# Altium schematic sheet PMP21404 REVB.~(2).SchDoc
size 431 x 279 mm; Date: Not shown in title block; ApprovedBy: Not shown in title block; CheckedBy: Not shown in title block; Author: Not shown in title block; CompanyName: Not shown in title block; Engineer: Not shown in title block; Organization: Not shown in title block; Address1: Not shown in title block; Address2: Not shown in title block; Address3: Not shown in title block; Address4: Not shown in title block; DocumentNumber: 1; Revision: Use project parameter SCH_Rev; SheetNumber: 1; SheetTotal: 1; PageSetup: Record=PageOptions¦CenterHorizontal=True¦CenterVertical=True¦PrintScale=1.00¦XCorrection=1.00¦YCorrection=1.00¦PrintKind=0¦BorderSize=5000000¦LeftOffset=0¦BottomOffset=0¦Orientation=2¦PaperLength=1000¦PaperWidth=1000¦Scale=100¦PaperSource=15¦PrintQuality=600¦MediaType=1¦DitherType=10¦PaperKind=Letter¦PrintScaleMode=1
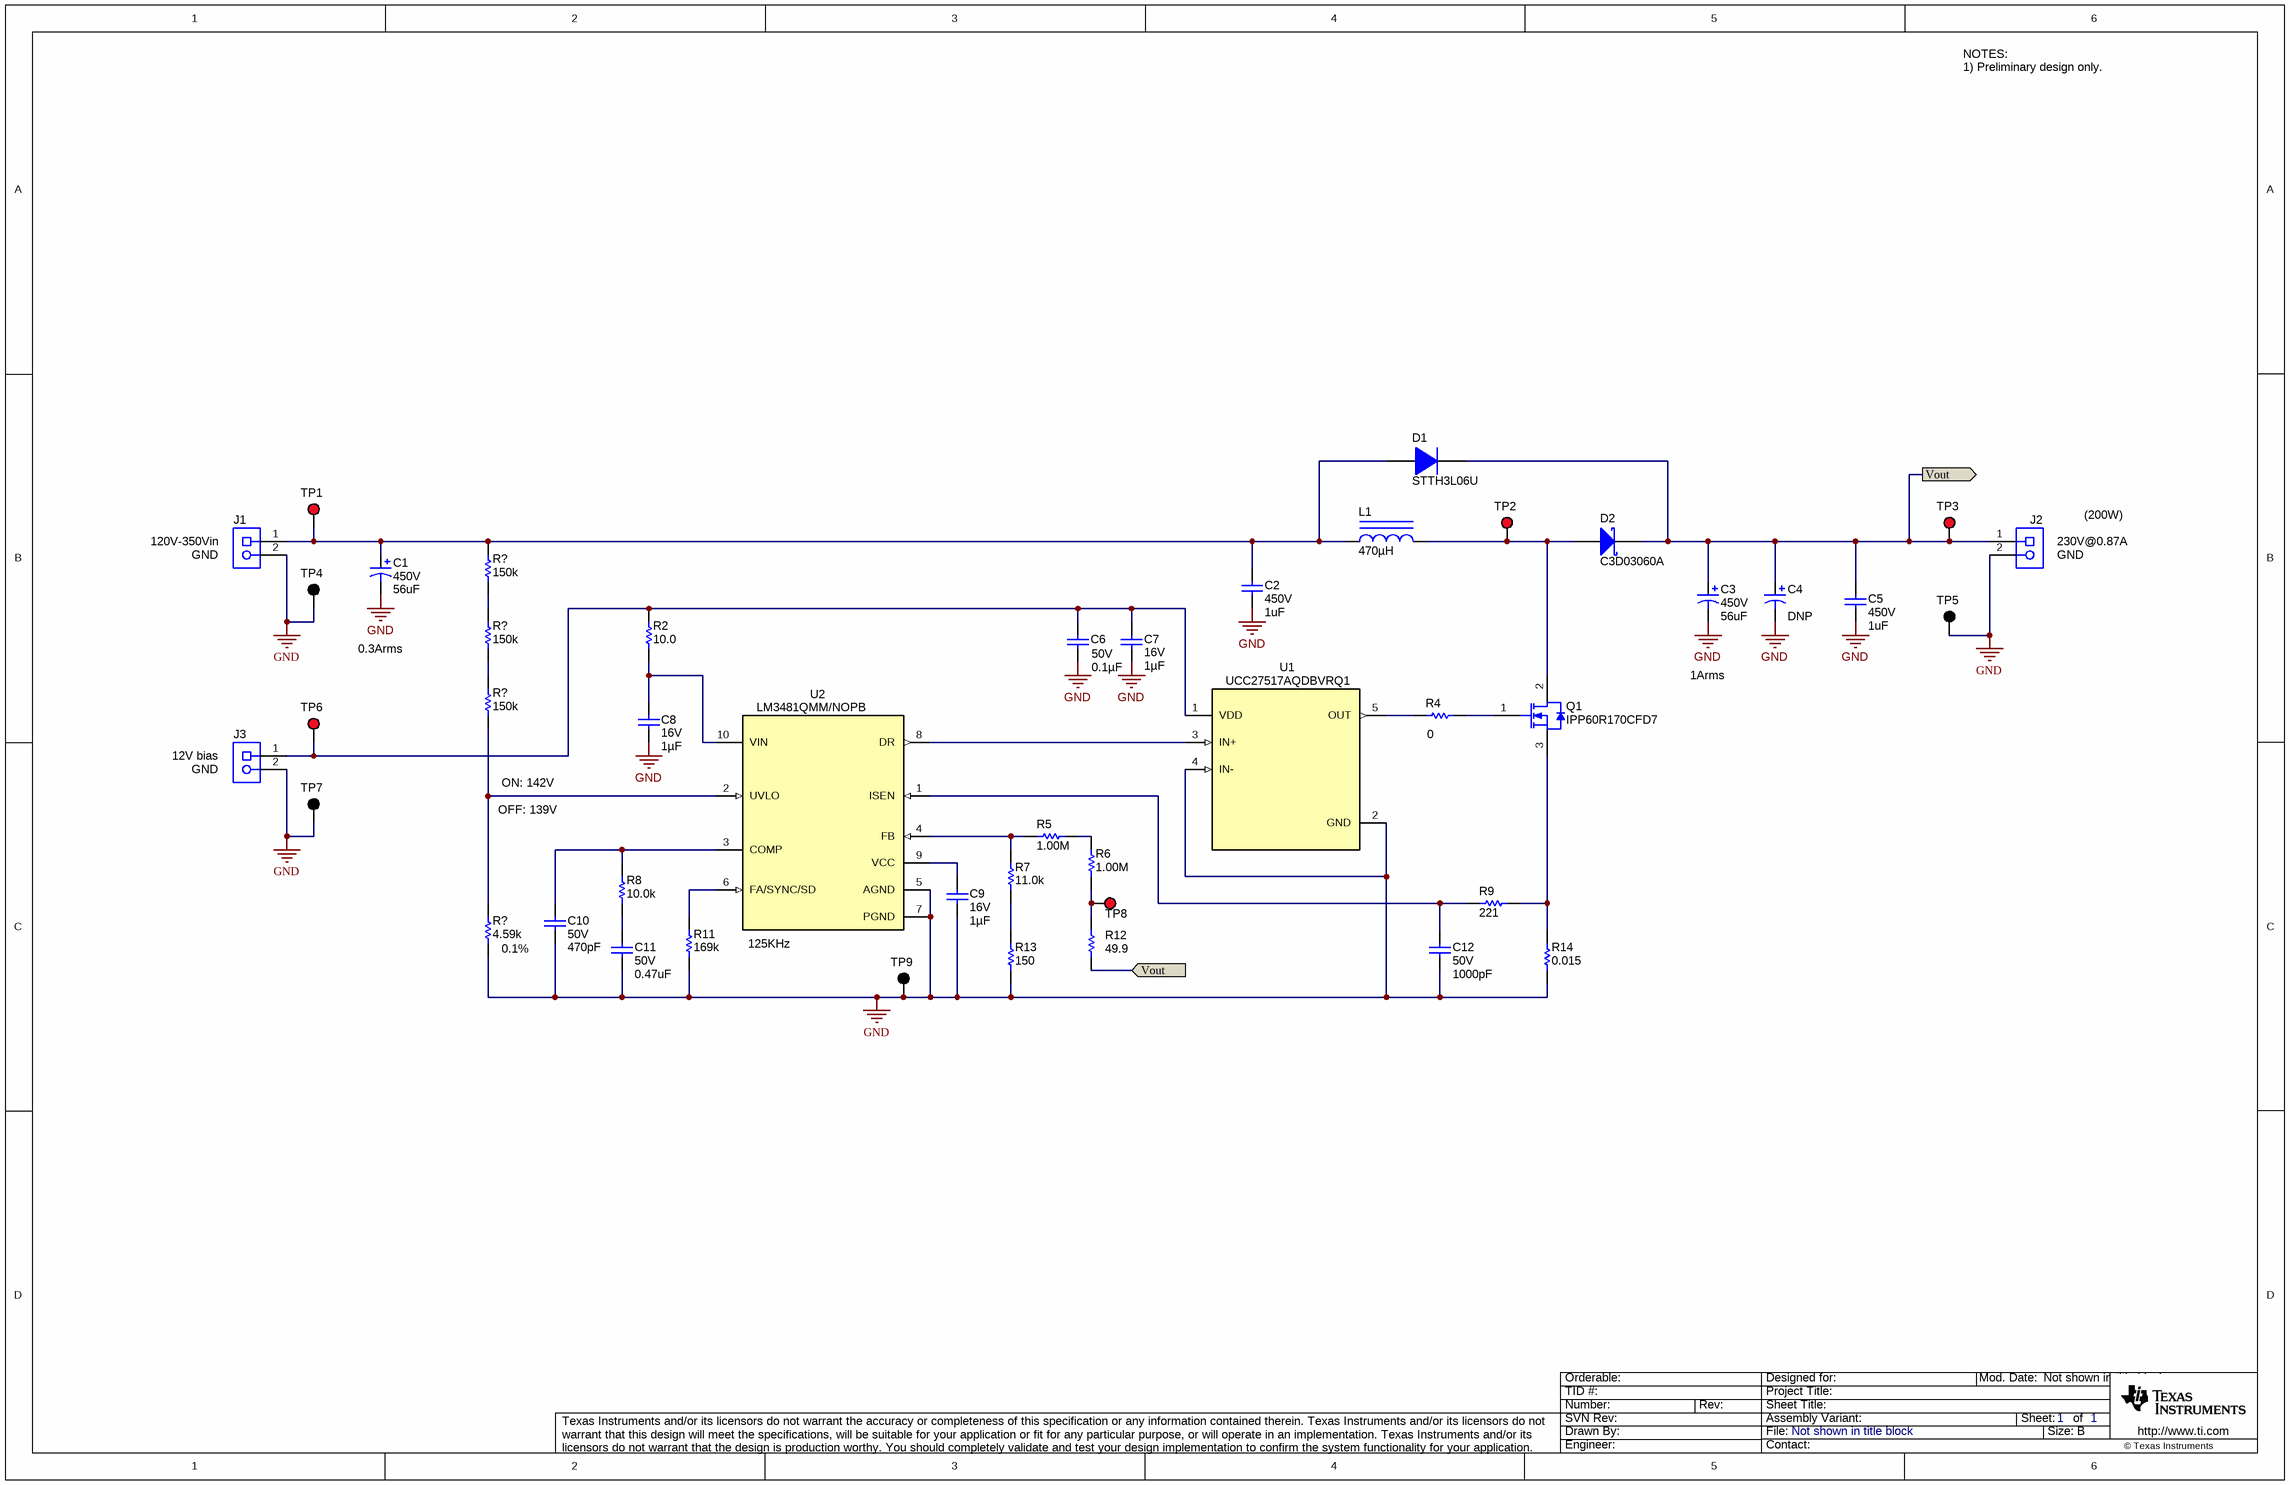
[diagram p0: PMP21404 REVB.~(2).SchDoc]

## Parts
(Parts that share a designator on the sheet are numbered #1, #2 ... from top to bottom, then left to right.)
C1  VDC_V: 450V  ValueDisplayed: 56uF  [Nichicon_2000x2500_Snap]  (hidden comment: LLS2W560MELY)
C2  VDC_V: 450V  ValueDisplayed: 1uF  [MPK_1800x950]  (hidden comment: 450MPK105J)
C3  VDC_V: 450V  ValueDisplayed: 56uF  [Nichicon_2000x2500_Snap]  (hidden comment: LLS2W560MELY)
C4  ValueDisplayed: DNP  [Nichicon_2000x2500_Snap]
C5  VDC_V: 450V  ValueDisplayed: 1uF  [MPK_1800x950]  (hidden comment: 450MPK105J)
C6  VDC_V: 50V  ValueDisplayed: 0.1µF  [0603]  (hidden comment: C0603C104K5RACAUTO)
C7  VDC_V: 16V  ValueDisplayed: 1µF  [0603]  (hidden comment: CGA3E1X7R1C105K080AC)
C8  VDC_V: 16V  ValueDisplayed: 1µF  [0603]  (hidden comment: CGA3E1X7R1C105K080AC)
C9  VDC_V: 16V  ValueDisplayed: 1µF  [0603]  (hidden comment: CGA3E1X7R1C105K080AC)
C10  VDC_V: 50V  ValueDisplayed: 470pF  [0603]  (hidden comment: GRM188R71H471KA01D)
C11  VDC_V: 50V  ValueDisplayed: 0.47uF  [0603]  (hidden comment: CGA3E3X7R1H474K080AB)
C12  VDC_V: 50V  ValueDisplayed: 1000pF  [0603]  (hidden comment: GRM188R71H102JA01D)
D1  STTH3L06U  [SMB]
D2  C3D03060A  [TO-220-2]
J1  Receptacle_2x1  [TERM_BLK_ED555-2DS]  (value not drawn)
J2  Receptacle_2x1  [TERM_BLK_ED555-2DS]  (value not drawn)
J3  Receptacle_2x1  [TERM_BLK_ED555-2DS]  (value not drawn)
L1  ValueDisplayed: 470µH  [Renco_RL1256-3_Pitch_750]  (hidden comment: RL-1256-3-470)
Q1  IPP60R170CFD7  [TO-220AB]
R2  ValueDisplayed: 10.0  [0603]  (hidden comment: CRCW060310R0FKEA)
R4  ValueDisplayed: 0  [0603]  (hidden comment: CRCW06030000Z0EA)
R5  ValueDisplayed: 1.00M  [1206]  (hidden comment: CRCW12061M00FKEA)
R6  ValueDisplayed: 1.00M  [1206]  (hidden comment: CRCW12061M00FKEA)
R7  ValueDisplayed: 11.0k  [0603]  (hidden comment: CRCW060311K0FKEA)
R8  ValueDisplayed: 10.0k  [0603]  (hidden comment: CRCW060310K0FKEA)
R9  value 221  [0603L]  (hidden comment: Resistor)
R11  ValueDisplayed: 169k  [0603]  (hidden comment: CRCW0603169KFKEA)
R12  value 49.9  [0603L]  (hidden comment: Resistor)
R13  ValueDisplayed: 150  [0603]  (hidden comment: CRCW0603150RFKEA)
R14  ValueDisplayed: 0.015  [1206]  (hidden comment: WSLP1206R0150FEA)
R?#1  ValueDisplayed: 150k  [1206]  (hidden comment: CRCW1206150KFKEA)
R?#2  ValueDisplayed: 150k  [1206]  (hidden comment: CRCW1206150KFKEA)
R?#3  ValueDisplayed: 150k  [1206]  (hidden comment: CRCW1206150KFKEA)
R?#4  Tolerance_%: 0.1%  ValueDisplayed: 4.59k  [0603]  (hidden comment: RT0603BRD074K59L)
TP1  5000  [Keystone5000]  (value not drawn)
TP2  5000  [Keystone5000]  (value not drawn)
TP3  5000  [Keystone5000]  (value not drawn)
TP4  5001  [Keystone5001]  (value not drawn)
TP5  5001  [Keystone5001]  (value not drawn)
TP6  5000  [Keystone5000]  (value not drawn)
TP7  5001  [Keystone5001]  (value not drawn)
TP8  5000  [Keystone5000]  (value not drawn)
TP9  5001  [Keystone5001]  (value not drawn)
U1  UCC27517AQDBVRQ1  [DBV0005A_N]
U2  LM3481QMM/NOPB  [DGS0010A_N]

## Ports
Vout

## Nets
GND: C1.2(-) C2.2 C3.2(-) C4.2(-) C5.2 C6.2 C7.2 C8.2 C9.2 C10.2 C11.2 C12.2 J1.2 J2.2 J3.2 R11.1 R13.1 R14.1 R?#4.1 TP4.1 TP5.1 TP7.1 TP9.1 U1.2(GND) U1.4(IN-) U2.5(AGND) U2.7(PGND)
Vout: C3.1(+) C4.1(+) C5.1 D1.1(K) D2.1(K) J2.1 R12.1 TP3.1 ; port Vout
NetC1_1: C1.1(+) C2.1 D1.2(A) J1.1 L1.1 R?#1.2 TP1.1
NetC6_1: C6.1 C7.1 J3.1 R2.1 TP6.1 U1.1(VDD)
NetC8_1: C8.1 R2.2 U2.10(VIN)
NetC9_1: C9.1 U2.9(VCC)
NetC10_1: C10.1 R8.2 U2.3(COMP)
NetC11_1: C11.1 R8.1
NetC12_1: C12.1 R9.2 U2.1(ISEN)
NetD2_2: D2.2(A) L1.2 Q1.2(D) TP2.1
NetQ1_1: Q1.1(G) R4.2
NetQ1_3: Q1.3(S) R9.1 R14.2
NetR4_1: R4.1 U1.5(OUT)
NetR5_1: R5.1 R7.2 U2.4(FB)
NetR5_2: R5.2 R6.2
NetR6_1: R6.1 R12.2 TP8.1
NetR7_1: R7.1 R13.2
NetR11_2: R11.2 U2.6(FA/SYNC/SD)
NetR?#1_1: R?#1.1 R?#2.2
NetR?#2_1: R?#2.1 R?#3.2
NetR?#3_1: R?#3.1 R?#4.2 U2.2(UVLO)
NetU1_3: U1.3(IN+) U2.8(DR)

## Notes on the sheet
- NOTES:
  1) Preliminary design only.
- (near J1) 120V-350Vin
- (near J1) GND
- (near J2) 230V@0.87A
- (near J2) GND
- (200W)
- 0.3Arms
- 1Arms
- (near J3) 12V bias
- (near J3) GND
- ON: 142V
- OFF: 139V
- (near U2) 125KHz

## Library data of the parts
C1 C3 = CMP-0010119-2: CAP, AL, 56 uF, 450 V, +/- 20%, TH; Manufacturer: Nichicon; TaMin_C: -25°C; Polarized: Y; SizeAreaWB_mm2: 484; Value1: Unknown; U/M: EA; Value: 56uF; TaMax_C: 85°C; SizeZ_mm: 27; SizeX_mm: 20; Cap_Case: 20x25mm; SizeArea_mm2: 400; CompType: Capacitor; AEC Qualified: N; Cap_F: 56µF; IRMS_A: 6.1dA; AEC Category: Q200
C2 C5 = CMP-0012307-3: CAP, Film, 1 uF, 450 V, +/- 5%, TH; Manufacturer: Rubycon; TaMin_C: -40°C; Polarized: N; Value1: Unknown; Value: 1uF; TaMax_C: 105°C; Cap_Case: 18x9.5mm; Cap_F: 1µF; AEC Category: Q200
C4 = CMP-0010119-2: CAP, AL, DNP; TaMin_C: -25°C; Polarized: Y; SizeAreaWB_mm2: 484; Value1: Unknown; U/M: EA; TaMax_C: 85°C; Tolerance_%: 20%; SizeZ_mm: 27; SizeX_mm: 20; Cap_Case: 20x25mm; SizeArea_mm2: 400; CompType: Capacitor; AEC Qualified: N; AEC Category: Q200
C6 = CMP-0079602-1: CAP, CERM, 0.1 µF, 50 V,+/- 10%, X7R, AEC-Q200 Grade 1, 0603; Manufacturer: Kemet; TaMin_C: -55°C; Polarized: N; SizeAreaWB_mm2: 4.68; U/M: EA; Value: 0.1uF; TaMax_C: 125°C; SizeZ_mm: 1; SizeX_mm: 1.6; SizeY_mm: 0.8; SizeArea_mm2: 1.28; CompType: Capacitor; AEC Qualified: Y; Cap_F: 100nF; AEC Category: Q200
C7-C9 = CMP-0079607-1: CAP, CERM, 1 µF, 16 V,+/- 10%, X7R, AEC-Q200 Grade 1, 0603; Manufacturer: TDK; TaMin_C: -55°C; Polarized: N; SizeAreaWB_mm2: 4.68; U/M: EA; Value: 1uF; TaMax_C: 125°C; SizeZ_mm: 1; SizeX_mm: 1.6; SizeY_mm: 0.8; SizeArea_mm2: 1.28; AEC Qualified: Y; AEC Category: Q200
C10 = CMP-0007455-4: CAP, CERM, 470 pF, 50 V, +/- 10%, X7R, 0603; Manufacturer: MuRata; TaMin_C: -55°C; Polarized: N; SizeAreaWB_mm2: 4.68; Value1: Unknown; U/M: EA; Value: 470pF; TaMax_C: 125°C; SizeZ_mm: 1; SizeX_mm: 1.6; SizeY_mm: 0.8; SizeArea_mm2: 1.28; AEC Category: Q200
C11 = CMP-0007096-4: CAP, CERM, 0.47 uF, 50 V, +/- 10%, X7R, AEC-Q200 Grade 1, 0603; Manufacturer: TDK; TaMin_C: -55°C; ESR_ohm: 0.01064; Polarized: N; SizeAreaWB_mm2: 4.68; Value1: 0.01064 ohm; U/M: EA; Value: 0.47uF; TaMax_C: 125°C; SizeZ_mm: 1; SizeX_mm: 1.6; SizeY_mm: 0.8; SizeArea_mm2: 1.28; AEC Qualified: Y; Cap_F: 470nF; IRMS_A: 1.59966A; AEC Category: Q200
C12 = CMP-0007431-4: CAP, CERM, 1000 pF, 50 V, +/- 5%, X7R, 0603; Manufacturer: MuRata; TaMin_C: -55°C; Polarized: N; SizeAreaWB_mm2: 4.68; Value1: Unknown; U/M: EA; Value: 1000pF; TaMax_C: 125°C; SizeZ_mm: 1; SizeX_mm: 1.6; SizeY_mm: 0.8; SizeArea_mm2: 1.28; Cap_F: 1nF; AEC Category: Q200
D1 = CMP-0077014-1: Diode, Ultrafast, 600 V, 3 A, SMB; Manufacturer: STMicroelectronics; SizeAreaWB_mm2: 44.156; Vr_V: 600V; SizeArea_mm2: 21.336; TJmax_C: 175°C; AEC Category: Q101; Value: 600V; SizeZ_mm: 2.6; Green_REACh: Incomplete; Io_A: 3A; Vf_V: 1.3V; SizeY_mm: 3.81; Green_Lifecycle: Not Set; U/M: EA; SizeX_mm: 5.6
D2 = CMP-0079543-1: Diode, Schottky, 600 V, 11 A, AEC-Q101, TH; Manufacturer: Cree; SizeAreaWB_mm2: 77.630025; Vr_V: 600V; SizeArea_mm2: 44.650025; AEC Qualified: Y; TJmax_C: 175°C; AEC Category: Q101; Value: 600V; SizeZ_mm: 20; Green_REACh: Incomplete; Io_A: 11A; SizeY_mm: 4.445; Green_Lifecycle: Active; SizeX_mm: 10.045; RJC_CperW: 3.2
J1-J3 = CMP-0074913-1: Terminal Block, 3.5mm Pitch, 2x1, TH; PartNumber: ED555/2DS; Manufacturer: On-Shore Technology; Cert_CULUS: Y; CNHeader: False; ContactFinish: Brass; CT: True; Current_A: 6A; Gender: Female; Green_Lifecycle: Active; Green_REACh: Passed; Pitch_mm: 3.5; Row_Count: 1; Shrouded: N; Voltage_V: 150V
L1 = CMP-0077831-1: Inductor, 470 µH, 4 A, 0.187 ohm, TH; Manufacturer: Renco Electronics; SizeAreaWB_mm2: 896.4036; Irms: 4A @ 40C rise; SizeArea_mm2: 780.6436; AEC Qualified: N; AEC Category: Q200; Value: 470uH; SizeZ_mm: 21.59; Imax_A: 4A; SizeY_mm: 27.94; Isat: 6A @ 5% inductance drop; DCR_ohm: 1.87d
Q1 = CMP-0001174-3: MOSFET, N-CH, 600 V, 51 A, TO-220AB; Alternate Manufacturer: None; Manufacturer: Infineon Technologies; SizeZ_mm: 19.4; ChType: N; Value2: 28 nC; VdsMax_V: 600V; SizeX_mm: 10.2; SizeY_mm: 4.5; Vgs_V: 20V; Value: 600V; SizeArea_mm2: 45.9; AEC Category: Q101; IdsMax_A: 51A; SizeAreaWB_mm2: 79.3; U/M: EA; QgTyp_nC: 28
R2 = CMP-0022003-4: RES, 10.0, 1%, 0.1 W, AEC-Q200 Grade 0, 0603; Manufacturer: Vishay-Dale; Power_W: 100mW; TempCo: 100 ppm/C; Value_Code: 10R0; Value: 10.0; EIA_Code: E96; Res_ohm: 10; SizeX_mm: 1.6; SizeY_mm: 0.8; SizeZ_mm: 1; Value2: 0.1W; SizeArea_mm2: 1.28; AEC Qualified: Y; VDC_V: 75V; AEC Category: Q200; AEC Grade: 0
R4 = CMP-0025697-4: RES, 0, 5%, 0.1 W, AEC-Q200 Grade 0, 0603; Manufacturer: Vishay-Dale; Power_W: 100mW; TempCo: 200 ppm/C; Value_Code: 0000; Value: 0; EIA_Code: E24; SizeX_mm: 1.6; SizeY_mm: 0.8; SizeZ_mm: 1; Value2: 0.1W; SizeArea_mm2: 1.28; CompType: Resistor; AEC Qualified: Y; VDC_V: 75V; AEC Category: Q200
R5 R6 = CMP-0016716-3: RES, 1.00 M, 1%, 0.25 W, AEC-Q200 Grade 0, 1206; Manufacturer: Vishay-Dale; Power_W: 250mW; TempCo: 100 ppm/C; Value_Code: 1M00; Value: 1.00Meg; EIA_Code: E96; Res_ohm: 1M; SizeX_mm: 3.2; SizeY_mm: 1.6; SizeZ_mm: 1.35; Value2: 0.25W; SizeArea_mm2: 5.12; AEC Qualified: Y; VDC_V: 200V; AEC Category: Q200; AEC Grade: 0
R7 = CMP-0022016-4: RES, 11.0 k, 1%, 0.1 W, AEC-Q200 Grade 0, 0603; Manufacturer: Vishay-Dale; Power_W: 100mW; TempCo: 100 ppm/C; Value_Code: 11k0; Value: 11.0k; EIA_Code: E96; Res_ohm: 11k; SizeX_mm: 1.6; SizeY_mm: 0.8; SizeZ_mm: 1; Value2: 0.1W; SizeArea_mm2: 1.28; AEC Qualified: Y; VDC_V: 75V; AEC Category: Q200; AEC Grade: 0
R8 = CMP-0021998-4: RES, 10.0 k, 1%, 0.1 W, AEC-Q200 Grade 0, 0603; Manufacturer: Vishay-Dale; Power_W: 100mW; TempCo: 100 ppm/C; Value_Code: 10k0; Value: 10.0k; EIA_Code: E96; Res_ohm: 10k; SizeX_mm: 1.6; SizeY_mm: 0.8; SizeZ_mm: 1; Value2: 0.1W; SizeArea_mm2: 1.28; AEC Qualified: Y; VDC_V: 75V; AEC Category: Q200; AEC Grade: 0
R9 = CMP-0022217-5: RES, 221, 1%, 0.1 W, AEC-Q200 Grade 0, 0603; PartNumber: CRCW0603221RFKEA; Manufacturer: Vishay-Dale; Value_Code: 221R; Power_W: 100mW; Value2: 0.1W; VDC_V: 75V; TempCo: 100 ppm/C; EIA_Code: E96; AEC Category: Q200; AEC Grade: 0; AEC Qualified: Y; SizeArea_mm2: 1.28; SizeX_mm: 1.6; SizeY_mm: 0.8; SizeZ_mm: 1
R11 = CMP-0022077-4: RES, 169 k, 1%, 0.1 W, AEC-Q200 Grade 0, 0603; Manufacturer: Vishay-Dale; Power_W: 100mW; TempCo: 100 ppm/C; Value: 169k; EIA_Code: E96; SizeX_mm: 1.6; SizeY_mm: 0.8; SizeZ_mm: 1; Value2: 0.1W; SizeArea_mm2: 1.28; AEC Qualified: Y; VDC_V: 75V; AEC Category: Q200; AEC Grade: 0
R12 = CMP-0022448-4: RES, 49.9, 1%, 0.1 W, AEC-Q200 Grade 0, 0603; PartNumber: CRCW060349R9FKEA; Manufacturer: Vishay-Dale; Value_Code: 49R9; Power_W: 100mW; Value2: 0.1W; VDC_V: 75V; TempCo: 100 ppm/C; EIA_Code: E96; AEC Category: Q200; AEC Grade: 0; AEC Qualified: Y; SizeArea_mm2: 1.28; SizeX_mm: 1.6; SizeY_mm: 0.8; SizeZ_mm: 1
R13 = CMP-0022061-5: RES, 150, 1%, 0.1 W, AEC-Q200 Grade 0, 0603; Manufacturer: Vishay-Dale; Power_W: 100mW; TempCo: 100 ppm/C; Value_Code: 150R; Value: 150; EIA_Code: E96; SizeX_mm: 1.6; SizeY_mm: 0.8; SizeZ_mm: 1; Value2: 0.1W; SizeArea_mm2: 1.28; AEC Qualified: Y; VDC_V: 75V; AEC Category: Q200; AEC Grade: 0
R14 = CMP-0018571-2: RES, 0.015, 1%, 1 W, 1206; Manufacturer: Vishay-Dale; Power_W: 1W; TempCo: 75 ppm/C; Value_Code: R015; U/M: EA; Value: 0.015; EIA_Code: E96; SizeX_mm: 3.2; SizeY_mm: 1.6; SizeZ_mm: 1.35; SizeArea_mm2: 5.12; AEC Category: Q200
R?#1-R?#3 = CMP-0016639-3: RES, 150 k, 1%, 0.25 W, AEC-Q200 Grade 0, 1206; Manufacturer: Vishay-Dale; Power_W: 250mW; TempCo: 100 ppm/C; Value: 150k; EIA_Code: E96; SizeX_mm: 3.2; SizeY_mm: 1.6; SizeZ_mm: 1.35; Value2: 0.25W; SizeArea_mm2: 5.12; AEC Qualified: Y; VDC_V: 200V; AEC Category: Q200; AEC Grade: 0
R?#4 = CMP-0024297-2: RES, 4.59 k, 0.1%, 0.1 W, 0603; Manufacturer: Yageo America; Power_W: 100mW; TempCo: 25 ppm/C; Value_Code: 4k59; U/M: EA; Value: 4.59k; EIA_Code: E192; SizeX_mm: 1.6; SizeY_mm: 0.8; SizeZ_mm: 1; Value2: 0.1W; SizeArea_mm2: 1.28; CompType: Resistor; VDC_V: 75V; AEC Category: Q200
TP1-TP3 TP6 TP8 = CMP-0055137-1: Test Point, Miniature, Red, TH; Manufacturer: Keystone; CNHeader: FALSE; ContactFinish: Silver; CT: TRUE; Green_Lifecycle: Active; Green_REACh: Passed
TP4 TP5 TP7 TP9 = CMP-0055138-1: Test Point, Miniature, Black, TH; Manufacturer: Keystone; CNHeader: FALSE; ContactFinish: Silver; CT: TRUE; Green_Lifecycle: Active; Green_REACh: Passed
U1 = CMP-0066947-1: 4A/4A Single Channel High-speed Low-side Gate Driver, DBV0005A (SOT-23-5); Alternate Manufacturer: Texas Instruments; Green_Lifecycle: Active; SizeAreaWB_mm2: 14.82; Green_REACh: Passed; U/M: EA; SizeZ_mm: 1.45; SizeX_mm: 2.8; SizeY_mm: 2.9; SizeArea_mm2: 8.12; CompType: IC
U2 = CMP-0071928-2: High Efficiency Low-Side N-Channel Controller for Switching Regulators, AEC-Q100 Grade 1, 10-pin Mini SOIC, 1000 Reel; Manufacturer: Texas Instruments; Alternate PartNumber: LM3481QMMX/NOPB; CompType: IC; AEC Category: Q200; AEC Qualified: Y; SizeAreaWB_mm2: 23.6; SizeArea_mm2: 14.7; SizeX_mm: 4.9; SizeY_mm: 3; SizeZ_mm: 1.1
